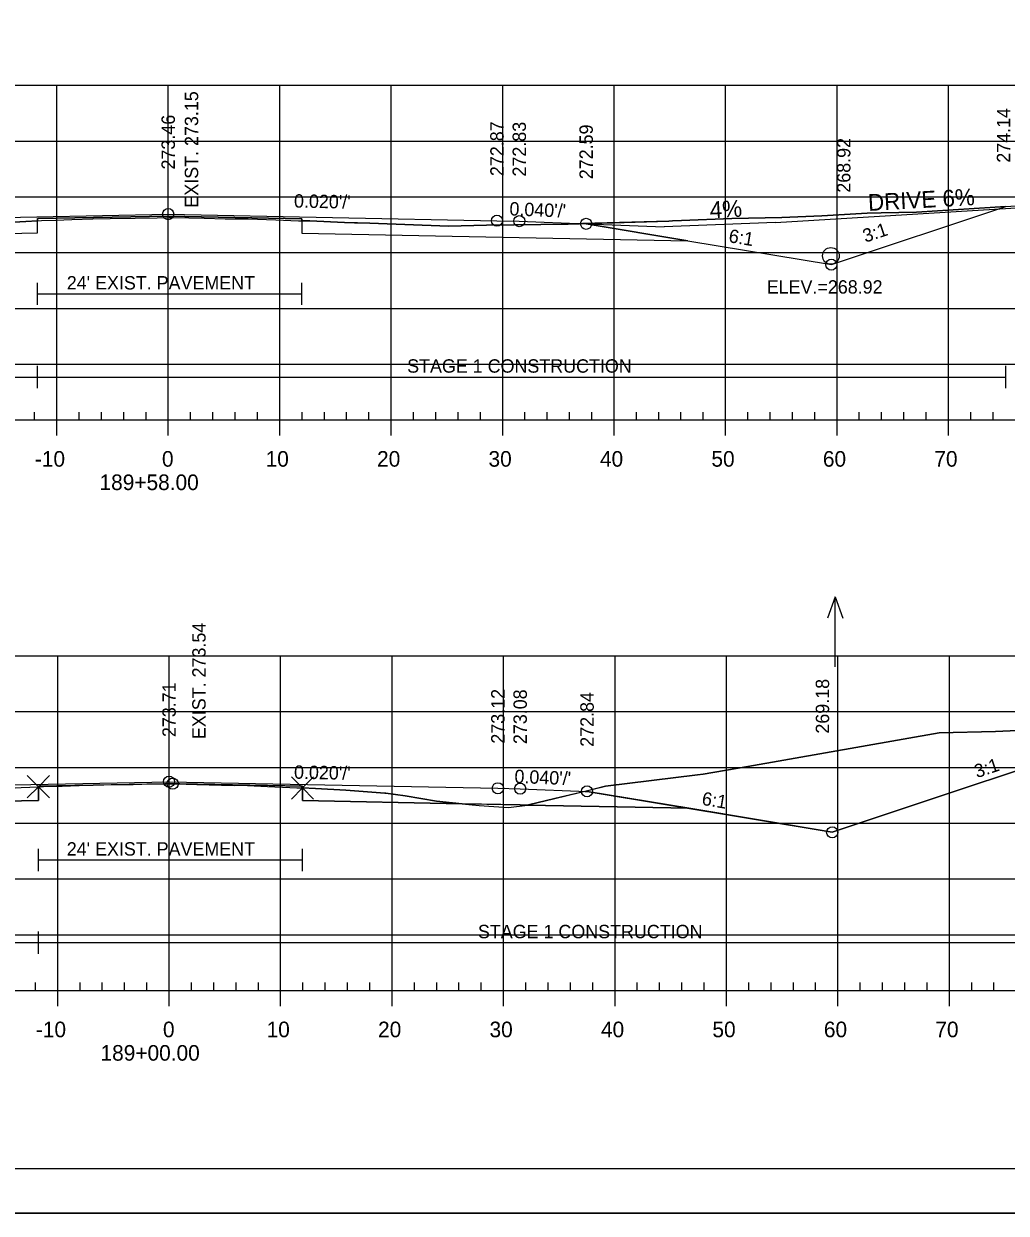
# Model space of a CAD drawing. Extents: x 1365647 to 1367999, y 387113 to 400173.
# Drawn here: x 1365881.8 to 1365970, y 388866.1 to 388972.8 of the extents above; entities that cross this region are included whole.
import ezdxf

# ---------------------------------------------------------------- set-up
doc = ezdxf.new("R2010")
doc.units = 0
for name, color, linetype in [('R_Alt Surface', 7, 'Continuous'), ('R_Axis', 7, 'Continuous'), ('R_Axis Annot', 7, 'Continuous'), ('R_Border', 7, 'Continuous'), ('R_Border Notes', 7, 'Continuous'), ('R_Contours', 7, 'Continuous'), ('R_Drive', 7, 'Continuous'), ('R_Exist Surface', 7, 'Continuous'), ('R_Fin Surface', 7, 'Continuous'), ('R_Fin Surface Annot', 7, 'Continuous'), ('R_Grid', 7, 'Continuous'), ('R_No Plot', 7, 'Continuous'), ('R_Proposed Const Limits', 7, 'Continuous'), ('R_Water', 7, 'Continuous'), ('R_Water Annot', 7, 'Continuous'), ('R_Xsect Elev', 7, 'Continuous')]:
    doc.layers.add(name, color=color, linetype=linetype)

msp = doc.modelspace()

# ---------------------------------------------------------------- linework, layer by layer
at = {"layer": 'R_Alt Surface'}
for points in [[(1365848.18, 388953.31), (1365863.3, 388953.61), (1365883.08, 388954.01), (1365883.08, 388955.3), (1365894.8, 388955.53), (1365906.8, 388955.29), (1365906.8, 388954), (1365926.3, 388953.61), (1365941.43, 388953.31)], [(1365848.26, 388902.41), (1365863.38, 388902.71), (1365883.15, 388903.1), (1365883.15, 388904.39), (1365894.88, 388904.63), (1365906.85, 388904.39), (1365906.85, 388903.1), (1365926.38, 388902.71), (1365941.51, 388902.41)]]:
    msp.add_lwpolyline(points, dxfattribs=at)
at = {"layer": 'R_Axis'}
for p, q in [((1365882.81, 388937.25), (1365882.81, 388937.95)), ((1365886.81, 388937.25), (1365886.81, 388937.95)), ((1365888.81, 388937.25), (1365888.81, 388937.95)), ((1365890.81, 388937.25), (1365890.81, 388937.95)), ((1365892.81, 388937.25), (1365892.81, 388937.95)), ((1365896.81, 388937.25), (1365896.81, 388937.95)), ((1365898.81, 388937.25), (1365898.81, 388937.95)), ((1365900.81, 388937.25), (1365900.81, 388937.95)), ((1365902.81, 388937.25), (1365902.81, 388937.95)), ((1365906.81, 388937.25), (1365906.81, 388937.95)), ((1365908.81, 388937.25), (1365908.81, 388937.95)), ((1365910.81, 388937.25), (1365910.81, 388937.95)), ((1365912.81, 388937.25), (1365912.81, 388937.95)), ((1365916.81, 388937.25), (1365916.81, 388937.95)), ((1365918.81, 388937.25), (1365918.81, 388937.95)), ((1365920.81, 388937.25), (1365920.81, 388937.95)), ((1365922.81, 388937.25), (1365922.81, 388937.95)), ((1365926.81, 388937.25), (1365926.81, 388937.95)), ((1365928.81, 388937.25), (1365928.81, 388937.95)), ((1365930.81, 388937.25), (1365930.81, 388937.95)), ((1365932.81, 388937.25), (1365932.81, 388937.95)), ((1365936.81, 388937.25), (1365936.81, 388937.95)), ((1365938.81, 388937.25), (1365938.81, 388937.95)), ((1365940.81, 388937.25), (1365940.81, 388937.95)), ((1365942.81, 388937.25), (1365942.81, 388937.95)), ((1365946.81, 388937.25), (1365946.81, 388937.95)), ((1365948.81, 388937.25), (1365948.81, 388937.95)), ((1365950.81, 388937.25), (1365950.81, 388937.95)), ((1365952.81, 388937.25), (1365952.81, 388937.95)), ((1365956.81, 388937.25), (1365956.81, 388937.95)), ((1365958.81, 388937.25), (1365958.81, 388937.95)), ((1365960.81, 388937.25), (1365960.81, 388937.95)), ((1365962.81, 388937.25), (1365962.81, 388937.95)), ((1365966.81, 388937.25), (1365966.81, 388937.95)), ((1365968.81, 388937.25), (1365968.81, 388937.95)), ((1365749.81, 388937.25), (1366039.81, 388937.25)), ((1365884.81, 388935.85), (1365884.81, 388937.25)), ((1365894.81, 388935.85), (1365894.81, 388937.25)), ((1365904.81, 388935.85), (1365904.81, 388937.25)), ((1365914.81, 388935.85), (1365914.81, 388937.25)), ((1365924.81, 388935.85), (1365924.81, 388937.25)), ((1365934.81, 388935.85), (1365934.81, 388937.25)), ((1365944.81, 388935.85), (1365944.81, 388937.25)), ((1365954.81, 388935.85), (1365954.81, 388937.25)), ((1365964.81, 388935.85), (1365964.81, 388937.25)), ((1365882.89, 388886.08), (1365882.89, 388886.78)), ((1365886.89, 388886.08), (1365886.89, 388886.78)), ((1365888.89, 388886.08), (1365888.89, 388886.78)), ((1365890.89, 388886.08), (1365890.89, 388886.78)), ((1365892.89, 388886.08), (1365892.89, 388886.78)), ((1365896.89, 388886.08), (1365896.89, 388886.78)), ((1365898.89, 388886.08), (1365898.89, 388886.78)), ((1365900.89, 388886.08), (1365900.89, 388886.78)), ((1365902.89, 388886.08), (1365902.89, 388886.78)), ((1365906.89, 388886.08), (1365906.89, 388886.78)), ((1365908.89, 388886.08), (1365908.89, 388886.78)), ((1365910.89, 388886.08), (1365910.89, 388886.78)), ((1365912.89, 388886.08), (1365912.89, 388886.78)), ((1365916.89, 388886.08), (1365916.89, 388886.78)), ((1365918.89, 388886.08), (1365918.89, 388886.78)), ((1365920.89, 388886.08), (1365920.89, 388886.78)), ((1365922.89, 388886.08), (1365922.89, 388886.78)), ((1365926.89, 388886.08), (1365926.89, 388886.78)), ((1365928.89, 388886.08), (1365928.89, 388886.78)), ((1365930.89, 388886.08), (1365930.89, 388886.78)), ((1365932.89, 388886.08), (1365932.89, 388886.78)), ((1365936.89, 388886.08), (1365936.89, 388886.78)), ((1365938.89, 388886.08), (1365938.89, 388886.78)), ((1365940.89, 388886.08), (1365940.89, 388886.78)), ((1365942.89, 388886.08), (1365942.89, 388886.78)), ((1365946.89, 388886.08), (1365946.89, 388886.78)), ((1365948.89, 388886.08), (1365948.89, 388886.78)), ((1365950.89, 388886.08), (1365950.89, 388886.78)), ((1365952.89, 388886.08), (1365952.89, 388886.78)), ((1365956.89, 388886.08), (1365956.89, 388886.78)), ((1365958.89, 388886.08), (1365958.89, 388886.78)), ((1365960.89, 388886.08), (1365960.89, 388886.78)), ((1365962.89, 388886.08), (1365962.89, 388886.78)), ((1365966.89, 388886.08), (1365966.89, 388886.78)), ((1365968.89, 388886.08), (1365968.89, 388886.78)), ((1365749.89, 388886.08), (1366039.89, 388886.08)), ((1365884.89, 388884.68), (1365884.89, 388886.08)), ((1365894.89, 388884.68), (1365894.89, 388886.08)), ((1365904.89, 388884.68), (1365904.89, 388886.08)), ((1365914.89, 388884.68), (1365914.89, 388886.08)), ((1365924.89, 388884.68), (1365924.89, 388886.08)), ((1365934.89, 388884.68), (1365934.89, 388886.08)), ((1365944.89, 388884.68), (1365944.89, 388886.08)), ((1365954.89, 388884.68), (1365954.89, 388886.08)), ((1365964.89, 388884.68), (1365964.89, 388886.08))]:
    msp.add_line(p, q, dxfattribs=at)
at = {"layer": 'R_Border'}
msp.add_line((1366052.27, 388870.08), (1365736.09, 388870.08), dxfattribs=at)
at = {"layer": 'R_Contours'}
for p, q in [((1365906.8, 388955.11), (1365906.8, 388955.29)), ((1365906.8, 388955.11), (1365906.8, 388954)), ((1365931.98, 388954.85), (1365932.3, 388954.83)), ((1365906.85, 388904.24), (1365906.85, 388903.1)), ((1365932.18, 388903.93), (1365932.38, 388903.93)), ((1365932.38, 388903.93), (1365932.18, 388903.93)), ((1365941.51, 388902.41), (1365932.38, 388903.93)), ((1365906.85, 388903.1), (1365921.19, 388902.81)), ((1365927.05, 388902.69), (1365941.51, 388902.41))]:
    msp.add_line(p, q, dxfattribs=at)
for points in [[(1365969.97, 388956.39), (1365961.93, 388955.88), (1365958.77, 388955.81), (1365957.5, 388955.79), (1365953.44, 388955.55), (1365949.85, 388955.39), (1365945.36, 388955.32), (1365940.86, 388955.14), (1365940.04, 388955.1), (1365939.72, 388955.08), (1365931.98, 388954.85)], [(1365932.3, 388954.83), (1365932.3, 388954.83), (1365941.43, 388953.31), (1365941.43, 388953.31), (1365954.3, 388951.17), (1365954.3, 388951.17), (1365969.97, 388956.39)], [(1365969.97, 388956.39), (1365969.97, 388956.39)], [(1365848.18, 388953.31), (1365863.3, 388953.61), (1365883.08, 388954.01), (1365883.08, 388955.11)], [(1365883.08, 388955.11), (1365882.04, 388955.05), (1365877.74, 388954.79), (1365876.69, 388954.66), (1365874.91, 388954.31), (1365874.72, 388954.31), (1365873.74, 388954.38), (1365871.4, 388954.31), (1365870.66, 388954.28), (1365869.59, 388954.31), (1365867.97, 388954.44), (1365866.54, 388954.55), (1365866.34, 388954.56), (1365865.22, 388954.56), (1365855.24, 388954.49)], [(1365906.8, 388955.29), (1365894.8, 388955.53), (1365883.08, 388955.3), (1365883.08, 388955.11)], [(1365883.08, 388955.11), (1365883.42, 388955.13), (1365884.72, 388955.16), (1365886.14, 388955.21), (1365888.04, 388955.27), (1365889.59, 388955.3), (1365891.84, 388955.34), (1365893.82, 388955.37), (1365894.88, 388955.4), (1365894.98, 388955.4), (1365895.28, 388955.4), (1365898.03, 388955.33), (1365899.91, 388955.28), (1365901.33, 388955.27), (1365901.98, 388955.27), (1365904.47, 388955.18), (1365906.48, 388955.11), (1365906.8, 388955.11)], [(1365931.98, 388954.85), (1365930.69, 388954.81), (1365923.37, 388954.7), (1365919.94, 388954.61), (1365912.9, 388954.89), (1365911.78, 388954.92), (1365911.53, 388954.93), (1365910.63, 388954.96), (1365907.51, 388955.09), (1365906.8, 388955.11)], [(1365906.8, 388954), (1365926.3, 388953.61), (1365941.43, 388953.31)], [(1365941.43, 388953.31), (1365932.3, 388954.83), (1365932.3, 388954.83), (1365931.98, 388954.85)], [(1365976.97, 388909.65), (1365976.94, 388909.65), (1365976.87, 388909.65), (1365969.03, 388909.29), (1365963.96, 388909.17), (1365946.8, 388906.16), (1365942.8, 388905.47), (1365942.29, 388905.41), (1365934.03, 388904.39), (1365932.18, 388903.93)], [(1365932.38, 388903.93), (1365941.51, 388902.41), (1365954.38, 388900.26), (1365982.22, 388909.54)], [(1365835.61, 388906.25), (1365837.8, 388906.31), (1365840.71, 388906.6), (1365846.86, 388905.99), (1365848.08, 388905.84), (1365850.96, 388905.37), (1365857.31, 388904.34), (1365860.17, 388904.05), (1365861.28, 388903.94), (1365863.53, 388903.44), (1365866.6, 388902.82), (1365871.97, 388903.15), (1365872.4, 388903.18), (1365872.61, 388903.22), (1365875.25, 388903.79), (1365876.31, 388903.93), (1365877.81, 388904.07), (1365881.6, 388904.28), (1365883.15, 388904.34), (1365883.15, 388903.1), (1365863.38, 388902.71), (1365848.26, 388902.41), (1365835.38, 388900.26)], [(1365921.19, 388902.81), (1365918.88, 388903.06), (1365916.05, 388903.53), (1365914.33, 388903.76), (1365914.24, 388903.77), (1365910.74, 388904.05), (1365908.02, 388904.19), (1365906.85, 388904.24)], [(1365932.18, 388903.93), (1365929.49, 388903.28), (1365927.14, 388902.71), (1365927.05, 388902.69)]]:
    msp.add_lwpolyline(points, dxfattribs=at)
for points in [[(1365927.05, 388902.69), (1365927.14, 388902.71), (1365929.49, 388903.28), (1365934.03, 388904.39), (1365942.29, 388905.41), (1365942.8, 388905.47), (1365946.8, 388906.16), (1365963.96, 388909.17), (1365969.03, 388909.29), (1365976.87, 388909.65), (1365976.94, 388909.65), (1365976.97, 388909.65), (1365982.22, 388909.54), (1365954.38, 388900.26), (1365941.51, 388902.41)], [(1365883.15, 388904.34), (1365883.32, 388904.35), (1365883.62, 388904.36), (1365885.28, 388904.41), (1365887.55, 388904.48), (1365888.08, 388904.49), (1365883.15, 388904.39)], [(1365888.08, 388904.49), (1365888.83, 388904.51), (1365891.65, 388904.56), (1365893.21, 388904.6), (1365894.34, 388904.62), (1365894.51, 388904.62)], [(1365894.51, 388904.62), (1365895.17, 388904.62), (1365894.88, 388904.63)], [(1365895.17, 388904.62), (1365895.21, 388904.62), (1365895.26, 388904.62), (1365895.42, 388904.62), (1365895.84, 388904.61)], [(1365895.84, 388904.61), (1365897.37, 388904.55), (1365899.57, 388904.48), (1365900.76, 388904.47), (1365901.31, 388904.48), (1365903.7, 388904.37), (1365905.72, 388904.27), (1365906.33, 388904.26), (1365906.85, 388904.24), (1365906.85, 388904.39)], [(1365906.85, 388904.24), (1365908.02, 388904.19), (1365910.74, 388904.05), (1365914.24, 388903.77), (1365914.33, 388903.76), (1365916.05, 388903.53), (1365918.88, 388903.06), (1365921.19, 388902.81), (1365906.85, 388903.1)], [(1365921.19, 388902.81), (1365922.07, 388902.72), (1365922.71, 388902.66), (1365925.34, 388902.47), (1365927.04, 388902.69), (1365927.05, 388902.69), (1365926.38, 388902.71)]]:
    msp.add_lwpolyline(points, close=True, dxfattribs=at)
at = {"layer": 'R_Drive'}
for p, q in [((1365949.29, 388954.95), (1365984.81, 388957.09)), ((1365932.3, 388954.83), (1365939.3, 388954.55)), ((1365949.29, 388954.95), (1365939.3, 388954.55))]:
    msp.add_line(p, q, dxfattribs=at)
at = {"layer": 'R_Exist Surface'}
for points in [[(1365877.74, 388954.79), (1365882.04, 388955.05), (1365883.08, 388955.11), (1365883.42, 388955.13), (1365884.72, 388955.16), (1365886.14, 388955.21), (1365888.04, 388955.27), (1365889.59, 388955.3), (1365891.84, 388955.34), (1365893.82, 388955.37), (1365894.88, 388955.4), (1365894.98, 388955.4), (1365895.28, 388955.4), (1365898.03, 388955.33), (1365899.91, 388955.28), (1365901.33, 388955.27), (1365901.98, 388955.27), (1365904.47, 388955.18), (1365906.48, 388955.11), (1365906.8, 388955.11), (1365907.51, 388955.09), (1365910.63, 388954.96), (1365911.53, 388954.93), (1365911.78, 388954.92), (1365912.9, 388954.89), (1365919.94, 388954.61), (1365923.37, 388954.7), (1365930.69, 388954.81), (1365939.72, 388955.08), (1365940.04, 388955.1), (1365940.86, 388955.14), (1365945.36, 388955.32), (1365949.85, 388955.39), (1365953.44, 388955.55), (1365957.5, 388955.79), (1365958.77, 388955.81), (1365961.93, 388955.88), (1365971.34, 388956.47)], [(1365881.6, 388904.28), (1365883.15, 388904.34), (1365883.32, 388904.35), (1365883.62, 388904.36), (1365885.28, 388904.41), (1365887.55, 388904.48), (1365888.83, 388904.51), (1365891.65, 388904.56), (1365893.21, 388904.6), (1365894.34, 388904.62), (1365895.21, 388904.62), (1365895.26, 388904.62), (1365895.42, 388904.62), (1365897.37, 388904.55), (1365899.57, 388904.48), (1365900.76, 388904.47), (1365901.31, 388904.48), (1365903.7, 388904.37), (1365905.72, 388904.27), (1365906.33, 388904.26), (1365906.85, 388904.24), (1365908.02, 388904.19), (1365910.74, 388904.05), (1365914.24, 388903.77), (1365914.33, 388903.76), (1365916.05, 388903.53), (1365918.88, 388903.06), (1365922.07, 388902.72), (1365922.71, 388902.66), (1365925.34, 388902.47), (1365927.04, 388902.69), (1365927.14, 388902.71), (1365929.49, 388903.28), (1365934.03, 388904.39), (1365942.29, 388905.41), (1365942.8, 388905.47), (1365946.8, 388906.16), (1365963.96, 388909.17), (1365969.03, 388909.29), (1365976.87, 388909.65)]]:
    msp.add_lwpolyline(points, dxfattribs=at)
at = {"layer": 'R_Fin Surface'}
for points in [[(1365810.51, 388954.54), (1365827.97, 388948.72), (1365827.97, 388948.72), (1365835.3, 388951.17), (1365848.17, 388953.31), (1365848.18, 388953.31), (1365848.18, 388953.31), (1365857.3, 388954.83), (1365863.3, 388955.07), (1365865.3, 388955.11), (1365865.31, 388955.11), (1365894.8, 388955.7), (1365894.81, 388955.7), (1365924.3, 388955.11), (1365926.3, 388955.07), (1365932.3, 388954.83), (1365932.3, 388954.83), (1365941.43, 388953.31), (1365941.43, 388953.31), (1365954.3, 388951.17), (1365954.3, 388951.17), (1365969.97, 388956.39)], [(1365804.83, 388906.43), (1365829.36, 388898.25), (1365835.38, 388900.26), (1365848.26, 388902.41), (1365857.38, 388903.93), (1365863.38, 388904.17), (1365865.38, 388904.21), (1365894.88, 388904.8), (1365924.38, 388904.21), (1365926.38, 388904.17), (1365932.38, 388903.93), (1365941.51, 388902.41), (1365954.38, 388900.26), (1365982.22, 388909.54)], [(1365857.38, 388903.93), (1365863.38, 388904.17), (1365865.38, 388904.21), (1365894.88, 388904.8), (1365924.38, 388904.21), (1365926.38, 388904.17), (1365932.38, 388903.93)]]:
    msp.add_lwpolyline(points, dxfattribs=at)
at = {"layer": 'R_Grid'}
for p, q in [((1365749.81, 388967.25), (1366039.81, 388967.25)), ((1365884.81, 388937.25), (1365884.81, 388967.25)), ((1365894.81, 388937.25), (1365894.81, 388967.25)), ((1365904.81, 388937.25), (1365904.81, 388967.25)), ((1365914.81, 388937.25), (1365914.81, 388967.25)), ((1365924.81, 388937.25), (1365924.81, 388967.25)), ((1365934.81, 388937.25), (1365934.81, 388967.25)), ((1365944.81, 388937.25), (1365944.81, 388967.25)), ((1365954.81, 388937.25), (1365954.81, 388967.25)), ((1365964.81, 388937.25), (1365964.81, 388967.25)), ((1365749.81, 388962.25), (1366039.81, 388962.25)), ((1365749.81, 388957.25), (1366039.81, 388957.25)), ((1365749.81, 388952.25), (1366039.81, 388952.25)), ((1365749.81, 388947.25), (1366039.81, 388947.25)), ((1365749.81, 388942.25), (1366039.81, 388942.25)), ((1365749.81, 388937.25), (1366039.81, 388937.25)), ((1365749.89, 388916.08), (1366039.89, 388916.08)), ((1365884.89, 388886.08), (1365884.89, 388916.08)), ((1365894.89, 388886.08), (1365894.89, 388916.08)), ((1365904.89, 388886.08), (1365904.89, 388916.08)), ((1365914.89, 388886.08), (1365914.89, 388916.08)), ((1365924.89, 388886.08), (1365924.89, 388916.08)), ((1365934.89, 388886.08), (1365934.89, 388916.08)), ((1365944.89, 388886.08), (1365944.89, 388916.08)), ((1365954.89, 388886.08), (1365954.89, 388916.08)), ((1365964.89, 388886.08), (1365964.89, 388916.08)), ((1365749.89, 388911.08), (1366039.89, 388911.08)), ((1365749.89, 388906.08), (1366039.89, 388906.08)), ((1365749.89, 388901.08), (1366039.89, 388901.08)), ((1365749.89, 388896.08), (1366039.89, 388896.08)), ((1365749.89, 388891.08), (1366039.89, 388891.08)), ((1365749.89, 388886.08), (1366039.89, 388886.08))]:
    msp.add_line(p, q, dxfattribs=at)
at = {"layer": 'R_No Plot'}
msp.add_line((1365723.69, 388866.1), (1366057.03, 388866.1), dxfattribs=at)
msp.add_lwpolyline([(1365723.69, 389079.44), (1366057.03, 389079.44), (1366057.03, 388866.1), (1365723.69, 388866.1)], close=True, dxfattribs=at)
for points in [[(1365883.15, 388904.34), (1365882.15, 388905.34), (1365883.15, 388904.34), (1365882.15, 388903.34), (1365883.15, 388904.34), (1365884.15, 388903.34), (1365883.15, 388904.34), (1365884.15, 388905.34)], [(1365906.85, 388904.24), (1365905.85, 388905.24), (1365906.85, 388904.24), (1365905.85, 388903.24), (1365906.85, 388904.24), (1365907.85, 388903.24), (1365906.85, 388904.24), (1365907.85, 388905.24)]]:
    msp.add_lwpolyline(points, dxfattribs=at)
for centre in [(1365894.8, 388955.7), (1365924.3, 388955.11), (1365926.3, 388955.07), (1365932.3, 388954.83), (1365954.3, 388951.17), (1365894.88, 388904.8), (1365894.88, 388904.8), (1365894.88, 388904.8), (1365894.88, 388904.8), (1365894.88, 388904.8), (1365895.21, 388904.62), (1365924.38, 388904.21), (1365924.38, 388904.21), (1365924.38, 388904.21), (1365924.38, 388904.21), (1365924.38, 388904.21), (1365926.38, 388904.17), (1365926.38, 388904.17), (1365926.38, 388904.17), (1365926.38, 388904.17), (1365926.38, 388904.17), (1365932.38, 388903.93), (1365932.38, 388903.93), (1365932.38, 388903.93), (1365932.38, 388903.93), (1365932.38, 388903.93), (1365954.38, 388900.26), (1365954.38, 388900.26), (1365954.38, 388900.26), (1365954.38, 388900.26), (1365954.38, 388900.26)]:
    msp.add_circle(centre, 0.5, dxfattribs=at)
at = {"layer": 'R_Proposed Const Limits'}
msp.add_lwpolyline([(1365932.38, 388903.93), (1365954.38, 388900.26), (1365982.22, 388909.54)], dxfattribs=at)
at = {"layer": 'R_Water'}
for p, q in [((1365883.08, 388947.55), (1365883.08, 388949.55)), ((1365906.8, 388947.55), (1365906.8, 388949.55)), ((1365883.08, 388948.55), (1365906.8, 388948.55)), ((1365883.08, 388940.08), (1365883.08, 388942.08)), ((1365969.97, 388940.08), (1365969.97, 388942.08)), ((1365810.51, 388941.08), (1365883.08, 388941.08)), ((1365883.08, 388941.08), (1365969.97, 388941.08)), ((1365883.15, 388896.78), (1365883.15, 388898.78)), ((1365906.85, 388896.78), (1365906.85, 388898.78)), ((1365883.15, 388897.78), (1365906.85, 388897.78)), ((1365883.15, 388889.37), (1365883.15, 388891.37)), ((1365804.83, 388890.37), (1365883.15, 388890.37)), ((1365883.15, 388890.37), (1365982.22, 388890.37))]:
    msp.add_line(p, q, dxfattribs=at)
msp.add_circle((1365954.26, 388951.95), 0.75, dxfattribs=at)
at = {"layer": 'R_Water Annot'}
for p, q in [((1365954.64, 388921.39), (1365953.94, 388919.47)), ((1365954.64, 388915.11), (1365954.64, 388921.39)), ((1365954.64, 388921.39), (1365955.34, 388919.47))]:
    msp.add_line(p, q, dxfattribs=at)

# ---------------------------------------------------------------- texts
at = {"layer": 'R_Axis Annot'}
for s, p in [('-10', (1365882.84, 388933.05)), ('0', (1365894.24, 388933.05)), ('10', (1365903.54, 388933.05)), ('20', (1365913.54, 388933.05)), ('30', (1365923.54, 388933.05)), ('40', (1365933.54, 388933.05)), ('50', (1365943.54, 388933.05)), ('60', (1365953.54, 388933.05)), ('70', (1365963.54, 388933.05)), ('189+58.00', (1365888.64, 388930.95)), ('-10', (1365882.93, 388881.88)), ('0', (1365894.33, 388881.88)), ('10', (1365903.63, 388881.88)), ('20', (1365913.63, 388881.88)), ('30', (1365923.63, 388881.88)), ('40', (1365933.63, 388881.88)), ('50', (1365943.63, 388881.88)), ('60', (1365953.63, 388881.88)), ('70', (1365963.63, 388881.88)), ('189+00.00', (1365888.73, 388879.78))]:
    msp.add_text(s, height=1.4, dxfattribs=at).set_placement(p)
at = {"layer": 'R_Border Notes'}
msp.add_text('ELEV.=268.92', height=1.2, dxfattribs=at).set_placement((1365948.5, 388948.57))
at = {"layer": 'R_Drive'}
for s, p in [('DRIVE 6%', (1365957.63, 388955.98)), ('4%', (1365943.43, 388955.32))]:
    msp.add_text(s, height=1.5, rotation=3.1665, dxfattribs=at).set_placement(p)
at = {"layer": 'R_Fin Surface Annot'}
for s, rotation, p in [('274.14', 90, (1365970.35, 388960.31)), ('273.46', 90, (1365895.4, 388959.7)), ('272.87', 90, (1365924.9, 388959.11)), ('272.83', 90, (1365926.9, 388959.07)), ('272.59', 90, (1365932.9, 388958.83)), ('268.92', 90, (1365956.01, 388957.62)), ("0.020'/'", 358.8542, (1365906.08, 388956.29)), ("0.040'/'", 357.7094, (1365925.4, 388955.59)), ('6:1', 350.5377, (1365945.03, 388953.19)), ('3:1', 18.4349, (1365957.35, 388953.13)), ('273.71', 90, (1365895.48, 388908.8)), ('273.71', 90, (1365895.48, 388908.8)), ('273.71', 90, (1365895.48, 388908.8)), ('269.18', 90, (1365954.1, 388909.11)), ('273.12', 90, (1365924.98, 388908.21)), ('273.12', 90, (1365924.98, 388908.21)), ('273.12', 90, (1365924.98, 388908.21)), ('273.08', 90, (1365926.98, 388908.17)), ('273.08', 90, (1365926.98, 388908.17)), ('273.08', 90, (1365926.98, 388908.17)), ('272.84', 90, (1365932.98, 388907.93)), ('272.84', 90, (1365932.98, 388907.93)), ('272.84', 90, (1365932.98, 388907.93)), ("0.020'/'", 358.8542, (1365906.08, 388905.07)), ('3:1', 18.4349, (1365967.36, 388905.11)), ("0.040'/'", 357.7094, (1365925.85, 388904.69)), ('6:1', 350.5377, (1365942.62, 388902.73))]:
    msp.add_text(s, height=1.2, rotation=rotation, dxfattribs=at).set_placement(p)
at = {"layer": 'R_Water'}
for s, p in [("24' EXIST. PAVEMENT", (1365885.7, 388948.94)), ('STAGE 1 CONSTRUCTION', (1365916.24, 388941.48)), ("24' EXIST. PAVEMENT", (1365885.7, 388898.17)), ('STAGE 1 CONSTRUCTION', (1365922.59, 388890.76))]:
    msp.add_text(s, height=1.2, dxfattribs=at).set_placement(p)
at = {"layer": 'R_Xsect Elev'}
for s, p in [('EXIST. 273.15', (1365897.49, 388956.28)), ('EXIST. 273.54', (1365898.16, 388908.62))]:
    msp.add_text(s, height=1.2, rotation=90, dxfattribs=at).set_placement(p)

doc.saveas('drawing.dxf')
